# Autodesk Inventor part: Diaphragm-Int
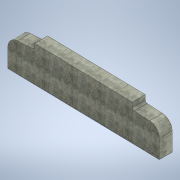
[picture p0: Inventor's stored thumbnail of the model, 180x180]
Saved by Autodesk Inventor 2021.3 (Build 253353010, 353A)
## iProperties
Created: 2021-10
Part Number: Diaphragm-Int
Material: Concrete, Precast
Document SubType Name: Modeling
Designer: u1426
Density: 2.40731 g/cm^3
Appearance: Smooth Precast Structural
Author: u1426
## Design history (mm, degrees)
sketch "Sketch1"
  geometry: L1 (-762, 1295.4)-(-762, 1261.45); L2 (-726.164, 1223.417)-(-419.726, 1205.177); L3 (-228.6, 1002.336)-(-228.6, 635); L4 (-3225.8, 697.992)-(-3225.8, 1065.328); L5 (-2692.4, 1324.442)-(-2692.4, 1358.392); L6 (-2728.236, 1286.409)-(-3034.674, 1268.169); L7 (-3225.8, 697.992)-(-228.6, 635); L8 (-3302, 1358.392)-(-3302, 215.392); L9 (-152.4, 1295.4)-(-152.4, 152.4); L10 (-2692.4, 1358.392)-(-3302, 1358.392); L11 (-762, 1295.4)-(-152.4, 1295.4); L12 (-3302, 215.392)-(-4872.129, 215.392); L13 (-152.4, 152.4)-(-1248.139, 152.4); L14 (-2692.4, 1358.392)-(-2692.4, 1396.492); L15 (-2692.4, 1396.492)-(-762, 1355.921); L16 (-762, 1355.921)-(-762, 1295.4); A1 r 203.2 centre (-431.8, 1002.336) between (-228.6, 1002.336) and (-419.726, 1205.177); A2 r 38.1 centre (-723.9, 1261.45) between (-762, 1261.45) and (-726.164, 1223.417); A3 r 203.2 centre (-3022.6, 1065.328) between (-3034.674, 1268.169) and (-3225.8, 1065.328); A4 r 38.1 centre (-2730.5, 1324.442) between (-2728.236, 1286.409) and (-2692.4, 1324.442); 5 further points
  constraints: 32 end point, 8 point on circle, 8 point on line, 8 tangent, 5 vertical, 4 centre point, 2 horizontal, 2 parallel, 2 perpendicular
  dimensions: "d12" = 69.85 distance of L1.start point (-762, 1225.55); "d16" = 31.75 vertical distance of point (-762, 1225.55) point (-228.6, 1193.8); "d23" = 203.2 radius of A1; "d24" = 38.1 radius of A2; "d68" = 533.4 horizontal distance of point (-2692.4, 1288.542) point (-3225.8, 1256.792); "d69" = 31.75 vertical distance of point (-2692.4, 1288.542) point (-3225.8, 1256.792); "d70" = 69.85 distance of point (-2692.4, 1288.542) L5.end; "d78" = 203.2 radius of A3; "d79" = 38.1 radius of A4; "d82" = 76.2 distance between parallel lines of L3 L9; "d83" = 76.2 distance between parallel lines of L4 L8; "d84" = 1143 distance of L9.start L9.end; "d85" = 1143 distance of L8.start L8.end (= d84); "d86" = 482.6 distance from line of L4.start L12 (= d87); "d87" = 482.6 distance from line of L3.end L13; "d88" = 62.992 distance between parallel lines of L13 L12 (= 0.02 x d89); "d89" = 3149.6 distance between parallel lines of L9 L8; "d90" = 38.1 distance of L5.end L14.end; "d91" = 152.4 distance from line of point (0, 0) L13; "d92" = 152.4 distance from line of point (0, 0) L9; "d93" = 533.4 distance between parallel lines of L3 L1
extrude "Extrusion9" new body sketch "Sketch1" stored distance "d94" = 254; taper "d95" = 0 deg
body "Solid4"
